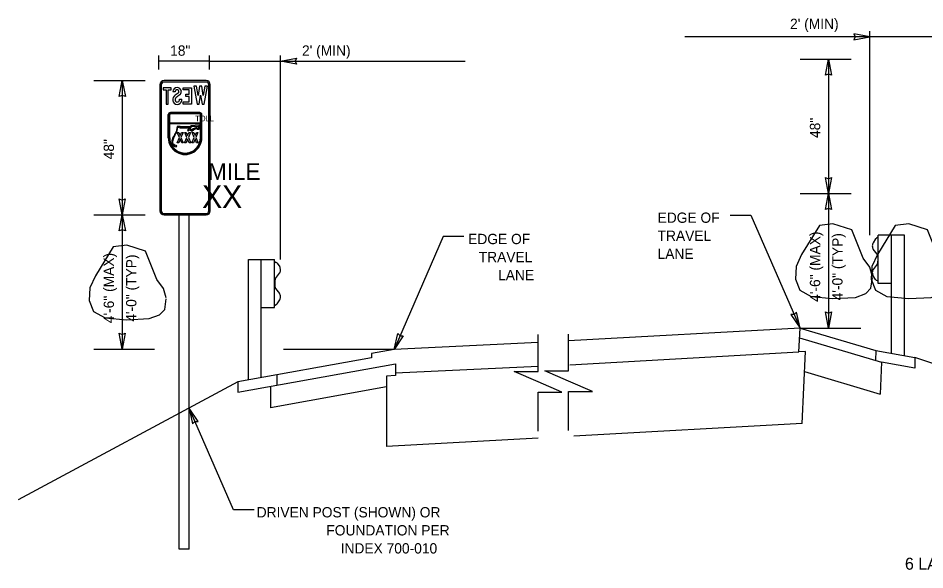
# Model space of a CAD drawing. Extents: x 57428 to 58066, y 11696 to 12105.
# Drawn here: x 57464.3 to 57710.6, y 11954.7 to 12104.5 of the extents above; entities that cross this region are included whole.
import ezdxf

# ---------------------------------------------------------------- set-up
doc = ezdxf.new("R2010")
doc.units = 0
for name, color, linetype in [('52', 7, 'Continuous'), ('62', 7, 'Continuous'), ('Default', 7, 'Continuous'), ('DimLines_dp', 7, 'Continuous'), ('NonPlottingEle_dp', 7, 'Continuous'), ('SignPanel', 7, 'Continuous'), ('TextTables', 7, 'Continuous'), ('XSGrdLine_ex', 7, 'Continuous')]:
    doc.layers.add(name, color=color, linetype=linetype)

msp = doc.modelspace()

# ---------------------------------------------------------------- linework, layer by layer
at = {"layer": '52'}
for p, q in [((57676.68, 12020.37), (57693.18, 12020.37)), ((57484.81, 12014.58), (57501.31, 12014.58)), ((57536.38, 12014.58), (57566.41, 12014.58))]:
    msp.add_line(p, q, dxfattribs=at)
at = {"layer": '62'}
for points in [[(57696.33, 12034.31), (57695.63, 12036.91), (57693.83, 12039.32), (57690.73, 12047.07), (57685.63, 12048.67), (57681.93, 12048.17), (57677.12, 12040.32), (57675.62, 12037.11), (57675.42, 12033.61), (57676.62, 12030.61), (57679.73, 12028.9), (57685.63, 12028.4), (57691.73, 12028.7), (57694.53, 12029.7), (57695.93, 12031.21), (57696.33, 12034.11)], [(57716.92, 12034.31), (57716.22, 12036.91), (57714.42, 12039.32), (57711.32, 12047.07), (57706.22, 12048.67), (57702.51, 12048.17), (57697.71, 12040.32), (57696.21, 12037.11), (57696.01, 12033.61), (57697.21, 12030.61), (57700.31, 12028.9), (57706.22, 12028.4), (57712.32, 12028.7), (57715.12, 12029.7), (57716.52, 12031.21), (57716.92, 12034.11)], [(57504.47, 12028.52), (57503.77, 12031.12), (57501.97, 12033.52), (57498.86, 12041.28), (57493.76, 12042.88), (57490.06, 12042.38), (57485.26, 12034.52), (57483.76, 12031.32), (57483.56, 12027.82), (57484.76, 12024.81), (57487.86, 12023.11), (57493.76, 12022.61), (57499.86, 12022.91), (57502.67, 12023.91), (57504.07, 12025.41), (57504.47, 12028.32)]]:
    msp.add_lwpolyline(points, dxfattribs=at)
at = {"layer": 'Default'}
for points in [[(57605.5, 11992.39), (57605.5, 12002.95), (57611.96, 12002.95), (57605.5, 12005.76), (57599.04, 12008.57), (57605.5, 12008.57), (57605.5, 12018.57)], [(57613.8, 11992.52), (57613.8, 12003.08), (57620.26, 12003.08), (57613.8, 12005.89), (57607.34, 12008.71), (57613.8, 12008.71), (57613.8, 12018.71)]]:
    msp.add_lwpolyline(points, dxfattribs=at)
at = {"layer": 'DimLines_dp'}
for p, q in [((57695.64, 12045.58), (57695.64, 12100.98)), ((57714.97, 12099.43), (57645.43, 12099.43)), ((57695.64, 12099.43), (57691.29, 12100.27)), ((57691.29, 12100.27), (57691.62, 12099.43)), ((57691.62, 12099.43), (57691.29, 12098.62)), ((57691.29, 12098.62), (57695.64, 12099.43)), ((57502.51, 12090.57), (57502.51, 12094.4)), ((57516.2, 12090.57), (57516.2, 12094.4)), ((57535.53, 12039), (57535.53, 12094.4)), ((57535.53, 12092.86), (57539.88, 12093.7)), ((57539.88, 12093.7), (57539.55, 12092.86)), ((57676.68, 12093.37), (57690.6, 12093.37)), ((57683.61, 12089.02), (57684.42, 12093.37)), ((57684.42, 12093.37), (57684.42, 12056.87)), ((57684.42, 12093.37), (57685.26, 12089.02)), ((57516.2, 12092.86), (57502.51, 12092.86)), ((57516.2, 12092.86), (57585.74, 12092.86)), ((57539.88, 12092.05), (57535.53, 12092.86)), ((57539.55, 12092.86), (57539.88, 12092.05)), ((57684.42, 12089.35), (57683.61, 12089.02)), ((57685.26, 12089.02), (57684.42, 12089.35)), ((57484.81, 12087.57), (57498.74, 12087.57)), ((57491.74, 12083.22), (57492.55, 12087.57)), ((57492.55, 12087.57), (57492.55, 12051.07)), ((57492.55, 12087.57), (57493.39, 12083.22)), ((57492.55, 12083.55), (57491.74, 12083.22)), ((57493.39, 12083.22), (57492.55, 12083.55)), ((57684.42, 12056.87), (57683.58, 12061.22)), ((57683.58, 12061.22), (57684.42, 12060.89)), ((57684.42, 12056.87), (57683.58, 12061.22)), ((57683.58, 12061.22), (57684.42, 12060.89)), ((57684.42, 12060.89), (57685.23, 12061.22)), ((57685.23, 12061.22), (57684.42, 12056.87)), ((57684.42, 12060.89), (57685.23, 12061.22)), ((57685.23, 12061.22), (57684.42, 12056.87)), ((57676.68, 12056.87), (57690.6, 12056.87)), ((57683.61, 12052.52), (57684.42, 12056.87)), ((57684.42, 12056.87), (57684.42, 12020.37)), ((57684.42, 12056.87), (57685.26, 12052.52)), ((57492.55, 12051.07), (57491.71, 12055.42)), ((57491.71, 12055.42), (57492.55, 12055.09)), ((57492.55, 12051.07), (57491.71, 12055.42)), ((57491.71, 12055.42), (57492.55, 12055.09)), ((57492.55, 12055.09), (57493.36, 12055.42)), ((57493.36, 12055.42), (57492.55, 12051.07)), ((57492.55, 12055.09), (57493.36, 12055.42)), ((57493.36, 12055.42), (57492.55, 12051.07)), ((57684.42, 12052.85), (57683.61, 12052.52)), ((57685.26, 12052.52), (57684.42, 12052.85)), ((57484.81, 12051.07), (57498.74, 12051.07)), ((57491.74, 12046.72), (57492.55, 12051.07)), ((57492.55, 12051.07), (57492.55, 12014.58)), ((57492.55, 12051.07), (57493.39, 12046.72)), ((57657.71, 12050.98), (57663.36, 12050.98)), ((57663.36, 12050.98), (57676.68, 12020.37)), ((57492.55, 12047.05), (57491.74, 12046.72)), ((57493.39, 12046.72), (57492.55, 12047.05)), ((57579.73, 12045.19), (57566.41, 12014.57)), ((57585.38, 12045.19), (57579.73, 12045.19)), ((57675.71, 12024.69), (57675.08, 12024.05)), ((57676.68, 12020.37), (57675.71, 12024.69)), ((57684.42, 12020.37), (57683.58, 12024.72)), ((57683.58, 12024.72), (57684.42, 12024.39)), ((57684.42, 12024.39), (57685.23, 12024.72)), ((57685.23, 12024.72), (57684.42, 12020.37)), ((57675.08, 12024.05), (57674.2, 12024.03)), ((57674.2, 12024.03), (57676.68, 12020.37)), ((57492.55, 12014.58), (57491.71, 12018.93)), ((57491.71, 12018.93), (57492.55, 12018.6)), ((57492.55, 12018.6), (57493.36, 12018.93)), ((57493.36, 12018.93), (57492.55, 12014.58)), ((57566.41, 12014.57), (57567.37, 12018.9)), ((57568.89, 12018.24), (57566.41, 12014.57)), ((57567.37, 12018.9), (57568.01, 12018.26)), ((57568.01, 12018.26), (57568.89, 12018.24)), ((57522.73, 11970.95), (57510.69, 11998.63)), ((57510.69, 11998.63), (57511.65, 11994.3)), ((57513.17, 11994.96), (57510.69, 11998.63)), ((57511.65, 11994.3), (57512.29, 11994.94)), ((57512.29, 11994.94), (57513.17, 11994.96)), ((57528.38, 11970.95), (57522.73, 11970.95))]:
    msp.add_line(p, q, dxfattribs=at)
at = {"layer": 'NonPlottingEle_dp'}
for p, q in [((57508.03, 11997.2), (57508.03, 12051.07)), ((57510.69, 11998.63), (57510.69, 12051.07)), ((57508.03, 11960.3), (57508.03, 11997.2)), ((57510.69, 11960.3), (57510.69, 11998.63)), ((57510.69, 11960.3), (57508.03, 11960.3))]:
    msp.add_line(p, q, dxfattribs=at)
at = {"layer": 'SignPanel'}
for p, q in [((57506.91, 12084.56), (57506.3, 12084.56)), ((57506.91, 12084.56), (57506.3, 12084.56)), ((57506.91, 12084.56), (57506.3, 12084.56)), ((57508.11, 12082.56), (57508.73, 12082.56)), ((57508.11, 12082.56), (57508.73, 12082.56)), ((57508.11, 12082.56), (57508.73, 12082.56)), ((57513.6, 12078.91), (57505.61, 12078.91)), ((57513.6, 12078.71), (57505.61, 12078.71)), ((57513.6, 12078.52), (57505.61, 12078.52)), ((57505.04, 12072.06), (57505.04, 12078.34)), ((57505.24, 12072.06), (57505.24, 12078.34)), ((57505.43, 12076.05), (57505.43, 12078.34)), ((57513.79, 12076.05), (57505.43, 12076.05)), ((57513.79, 12076.05), (57513.79, 12078.34)), ((57513.98, 12072.06), (57513.98, 12078.34)), ((57514.17, 12072.06), (57514.17, 12078.34)), ((57505.43, 12072.06), (57505.43, 12075.86)), ((57513.79, 12075.86), (57505.43, 12075.86)), ((57507.16, 12073.69), (57506.71, 12072.96)), ((57506.94, 12072.9), (57507.38, 12073.6)), ((57507.49, 12075.12), (57507.16, 12073.69)), ((57507.38, 12073.6), (57507.68, 12074.89)), ((57508.23, 12075.12), (57507.49, 12075.12)), ((57507.68, 12074.89), (57508.11, 12074.89)), ((57508.11, 12074.89), (57508.21, 12074.74)), ((57508.21, 12074.74), (57511.22, 12074.74)), ((57508.33, 12074.97), (57508.23, 12075.12)), ((57511.06, 12074.97), (57508.33, 12074.97)), ((57510.77, 12074.45), (57510.27, 12074.11)), ((57510.27, 12074.11), (57510.4, 12073.92)), ((57510.4, 12073.92), (57510.77, 12074.17)), ((57511.38, 12074.09), (57510.77, 12074.45)), ((57510.77, 12074.17), (57511.41, 12073.8)), ((57511.19, 12075.31), (57511.06, 12074.97)), ((57513.57, 12075.5), (57511.19, 12075.31)), ((57511.22, 12074.74), (57511.36, 12075.09)), ((57511.36, 12075.09), (57513.3, 12075.24)), ((57511.83, 12074.5), (57511.38, 12074.09)), ((57511.41, 12073.8), (57511.95, 12074.3)), ((57512.75, 12074.8), (57511.83, 12074.5)), ((57511.95, 12074.3), (57512.7, 12074.55)), ((57512.32, 12075.16), (57512.32, 12075.16)), ((57512.7, 12074.55), (57512.95, 12074.35)), ((57513.02, 12074.59), (57512.75, 12074.8)), ((57512.95, 12074.35), (57513.41, 12074.41)), ((57513.2, 12074.61), (57513.02, 12074.59)), ((57513.3, 12075.24), (57513.2, 12074.61)), ((57513.41, 12074.41), (57513.57, 12075.5)), ((57513.79, 12072.06), (57513.79, 12075.86)), ((57506.3, 12072.11), (57506.05, 12071.18)), ((57506.05, 12071.18), (57506.05, 12070.32)), ((57506.28, 12071.15), (57506.51, 12072.01)), ((57506.28, 12070.43), (57506.28, 12071.15)), ((57506.71, 12072.78), (57506.3, 12072.11)), ((57506.51, 12072.01), (57506.94, 12072.72)), ((57506.71, 12072.96), (57506.71, 12072.78)), ((57506.94, 12072.72), (57506.94, 12072.9)), ((57506.05, 12070.32), (57506.8, 12069.7)), ((57506.9, 12069.92), (57506.28, 12070.43)), ((57506.8, 12069.7), (57507.16, 12069.62)), ((57507.11, 12069.87), (57506.9, 12069.92)), ((57507.25, 12069.96), (57507.11, 12069.87)), ((57507.16, 12069.62), (57507.38, 12069.78)), ((57507.38, 12069.78), (57507.25, 12069.96))]:
    msp.add_line(p, q, dxfattribs=at)
for points in [[(57502.76, 12086.43), (57502.76, 12052.21)], [(57503.14, 12086.43), (57503.14, 12052.21)], [(57515.31, 12087.57), (57503.9, 12087.57)], [(57515.31, 12087.19), (57503.9, 12087.19)], [(57516.07, 12052.21), (57516.07, 12086.43)], [(57516.45, 12052.21), (57516.45, 12086.43)], [(57503.9, 12051.45), (57515.31, 12051.45)], [(57503.9, 12051.07), (57515.31, 12051.07)]]:
    msp.add_lwpolyline(points, dxfattribs=at)
for points in [[(57514.54, 12083.53), (57514.14, 12086.1), (57513.53, 12086.1), (57513.13, 12083.53), (57512.68, 12086.1), (57511.98, 12086.1), (57512.86, 12081.14), (57513.45, 12081.14), (57513.84, 12083.62), (57514.23, 12081.14), (57514.81, 12081.14), (57515.69, 12086.1), (57515, 12086.1)], [(57514.54, 12083.53), (57514.14, 12086.1), (57513.53, 12086.1), (57513.13, 12083.53), (57512.68, 12086.1), (57511.98, 12086.1), (57512.86, 12081.14), (57513.45, 12081.14), (57513.84, 12083.62), (57514.23, 12081.14), (57514.81, 12081.14), (57515.69, 12086.1), (57515, 12086.1)], [(57514.54, 12083.53), (57514.14, 12086.1), (57513.53, 12086.1), (57513.13, 12083.53), (57512.68, 12086.1), (57511.98, 12086.1), (57512.86, 12081.14), (57513.45, 12081.14), (57513.84, 12083.62), (57514.23, 12081.14), (57514.81, 12081.14), (57515.69, 12086.1), (57515, 12086.1)], [(57505.05, 12085.02), (57505.87, 12085.02), (57505.87, 12085.65), (57503.61, 12085.65), (57503.61, 12085.02), (57504.43, 12085.02), (57504.43, 12081.14), (57505.05, 12081.14)], [(57505.05, 12085.02), (57505.87, 12085.02), (57505.87, 12085.65), (57503.61, 12085.65), (57503.61, 12085.02), (57504.43, 12085.02), (57504.43, 12081.14), (57505.05, 12081.14)], [(57505.05, 12085.02), (57505.87, 12085.02), (57505.87, 12085.65), (57503.61, 12085.65), (57503.61, 12085.02), (57504.43, 12085.02), (57504.43, 12081.14), (57505.05, 12081.14)], [(57510.76, 12081.78), (57510.76, 12083.22), (57509.79, 12083.22), (57509.79, 12083.85), (57510.76, 12083.85), (57510.76, 12085.02), (57509.12, 12085.02), (57509.12, 12085.65), (57511.38, 12085.65), (57511.38, 12081.14), (57509.12, 12081.14), (57509.12, 12081.78)], [(57510.76, 12081.78), (57510.76, 12083.22), (57509.79, 12083.22), (57509.79, 12083.85), (57510.76, 12083.85), (57510.76, 12085.02), (57509.12, 12085.02), (57509.12, 12085.65), (57511.38, 12085.65), (57511.38, 12081.14), (57509.12, 12081.14), (57509.12, 12081.78)], [(57510.76, 12081.78), (57510.76, 12083.22), (57509.79, 12083.22), (57509.79, 12083.85), (57510.76, 12083.85), (57510.76, 12085.02), (57509.12, 12085.02), (57509.12, 12085.65), (57511.38, 12085.65), (57511.38, 12081.14), (57509.12, 12081.14), (57509.12, 12081.78)], [(57508.69, 12070.64), (57508.28, 12071.62), (57507.87, 12070.64), (57507.44, 12070.64), (57508.06, 12072.13), (57507.49, 12073.49), (57507.92, 12073.49), (57508.28, 12072.64), (57508.64, 12073.49), (57509.06, 12073.49), (57508.49, 12072.13), (57509.11, 12070.64)], [(57510.7, 12070.64), (57510.29, 12071.62), (57509.88, 12070.64), (57509.46, 12070.64), (57510.08, 12072.13), (57509.51, 12073.49), (57509.93, 12073.49), (57510.29, 12072.64), (57510.65, 12073.49), (57511.08, 12073.49), (57510.51, 12072.13), (57511.13, 12070.64)], [(57512.72, 12070.64), (57512.31, 12071.62), (57511.9, 12070.64), (57511.47, 12070.64), (57512.1, 12072.13), (57511.52, 12073.49), (57511.95, 12073.49), (57512.31, 12072.64), (57512.67, 12073.49), (57513.09, 12073.49), (57512.52, 12072.13), (57513.14, 12070.64)]]:
    msp.add_lwpolyline(points, close=True, dxfattribs=at)
for centre, radius, start, end in [((57503.9, 12086.43), 1.14, 90, 180), ((57503.9, 12086.43), 0.76, 90, 180), ((57515.31, 12086.43), 1.14, 0, 90), ((57515.31, 12086.43), 0.76, 0, 90), ((57503.9, 12052.21), 1.14, 180, 270), ((57503.9, 12052.21), 0.76, 180, 270), ((57515.31, 12052.21), 1.14, 270, 0), ((57515.31, 12052.21), 0.76, 270, 0)]:
    msp.add_arc(centre, radius, start, end, dxfattribs=at)
for centre, major_axis, ratio, start_param, end_param in [((57507.45, 12084.54), (0, -1.17), 0.981197, 1.634182, 4.688511), ((57507.45, 12084.54), (0, -1.17), 0.981197, 1.634182, 4.688511), ((57507.45, 12084.54), (0, -1.17), 0.981197, 1.634182, 4.688511), ((57509.76, 12080.4), (0, -4.32), 0.981197, 3.642536, 3.961892), ((57509.76, 12080.4), (0, -4.32), 0.981197, 3.642536, 3.961892), ((57509.76, 12080.4), (0, -4.32), 0.981197, 3.642536, 3.961892), ((57507.45, 12084.52), (0, -0.55), 0.981197, 2.28404, 4.637874), ((57507.45, 12084.52), (0, -0.55), 0.981197, 2.28404, 4.637874), ((57507.45, 12084.52), (0, -0.55), 0.981197, 2.28404, 4.637874), ((57510.3, 12079.71), (0, -4.56), 0.981197, 3.63779, 3.909641), ((57510.3, 12079.71), (0, -4.56), 0.981197, 3.63779, 3.909641), ((57510.3, 12079.71), (0, -4.56), 0.981197, 3.63779, 3.909641), ((57507.52, 12084.59), (0, -0.453), 0.981197, 0.484634, 2.267813), ((57507.52, 12084.59), (0, -0.453), 0.981197, 0.484634, 2.267813), ((57507.52, 12084.59), (0, -0.453), 0.981197, 0.484634, 2.267813), ((57507.56, 12084.57), (0, -1.05), 0.981197, 0.629826, 1.606762), ((57507.56, 12084.57), (0, -1.05), 0.981197, 0.629826, 1.606762), ((57507.56, 12084.57), (0, -1.05), 0.981197, 0.629826, 1.606762), ((57507.64, 12082.37), (0, -1.4), 0.981197, 3.939023, 5.163791), ((57507.64, 12082.37), (0, -1.4), 0.981197, 3.939023, 5.163791), ((57507.64, 12082.37), (0, -1.4), 0.981197, 3.939023, 5.163791), ((57507.49, 12082.31), (0, -1.23), 0.981197, 5.173086, 6.638731), ((57507.49, 12082.31), (0, -1.23), 0.981197, 5.173086, 6.638731), ((57507.49, 12082.31), (0, -1.23), 0.981197, 5.173086, 6.638731), ((57507.65, 12082.37), (0, -0.78), 0.981197, 3.79238, 5.170369), ((57507.65, 12082.37), (0, -0.78), 0.981197, 3.79238, 5.170369), ((57507.65, 12082.37), (0, -0.78), 0.981197, 3.79238, 5.170369), ((57507.46, 12082.29), (0, -0.572), 0.981197, 5.194718, 7.162991), ((57507.46, 12082.29), (0, -0.572), 0.981197, 5.194718, 7.162991), ((57507.46, 12082.29), (0, -0.572), 0.981197, 5.194718, 7.162991), ((57507.23, 12082.52), (0, -0.897), 0.981197, 0.859453, 1.616836), ((57507.29, 12082.49), (0, -1.47), 0.981197, 0.439911, 1.615229), ((57507.23, 12082.52), (0, -0.897), 0.981197, 0.859453, 1.616836), ((57507.29, 12082.49), (0, -1.47), 0.981197, 0.439911, 1.615229), ((57507.23, 12082.52), (0, -0.897), 0.981197, 0.859453, 1.616836), ((57507.29, 12082.49), (0, -1.47), 0.981197, 0.439911, 1.615229), ((57505.62, 12078.33), (0, 0.57), 0.9997, 0, 1.570796), ((57505.62, 12078.33), (0, 0.38), 0.9997, 0, 1.570796), ((57505.62, 12078.33), (0, 0.19), 0.9997, 0, 1.570796), ((57513.6, 12078.33), (0, 0.57), 0.9997, 4.712389, 6.283185), ((57513.6, 12078.33), (0, 0.38), 0.9997, 4.712389, 6.283185), ((57513.6, 12078.33), (0, 0.19), 0.9997, 4.712389, 6.283185), ((57509.61, 12072.06), (0, 4.56), 0.9997, 1.570796, 4.712389), ((57509.61, 12072.06), (0, 4.37), 0.9997, 1.570796, 4.712389), ((57509.61, 12072.06), (0, 4.18), 0.9997, 1.570796, 4.712389)]:
    msp.add_ellipse(centre, major_axis=major_axis, ratio=ratio, start_param=start_param, end_param=end_param, dxfattribs=at)
at = {"layer": 'XSGrdLine_ex'}
for p, q in [((57697.23, 12044.57), (57696.53, 12043.53)), ((57697.92, 12045.01), (57697.45, 12044.78)), ((57705.04, 12045.58), (57697.93, 12045.58)), ((57697.93, 12032.49), (57697.93, 12045.58)), ((57701.54, 12013.47), (57701.54, 12045.58)), ((57705.04, 12012.84), (57705.04, 12045.58)), ((57697.63, 12040.42), (57696.56, 12041.82)), ((57697.86, 12039.6), (57697.86, 12038.5)), ((57526.81, 12006.27), (57526.81, 12039)), ((57526.81, 12039), (57533.91, 12039)), ((57530.3, 12006.9), (57530.3, 12039)), ((57533.91, 12025.91), (57533.91, 12039)), ((57533.92, 12038.43), (57534.39, 12038.2)), ((57534.62, 12037.99), (57535.31, 12036.95)), ((57697.63, 12037.7), (57696.56, 12036.29)), ((57534.21, 12033.84), (57535.28, 12035.24)), ((57697.23, 12033.54), (57696.53, 12034.57)), ((57533.99, 12033.02), (57533.99, 12031.92)), ((57697.92, 12033.1), (57697.45, 12033.31)), ((57701.54, 12032.49), (57697.93, 12032.49)), ((57534.21, 12031.12), (57535.28, 12029.71)), ((57533.92, 12026.52), (57534.39, 12026.73)), ((57534.62, 12026.96), (57535.31, 12027.99)), ((57530.3, 12025.91), (57533.91, 12025.91)), ((57676.68, 12020.37), (57613.8, 12016.89)), ((57676.39, 12013.86), (57676.68, 12020.37)), ((57676.68, 12020.37), (57697.32, 12014.23)), ((57676.56, 12017.7), (57698.85, 12011.07)), ((57566.41, 12014.57), (57560.25, 12013.46)), ((57560.25, 12012.29), (57523.97, 12005.76)), ((57560.25, 12013.46), (57560.25, 12012.29)), ((57614.16, 12010.41), (57676.39, 12013.86)), ((57678.14, 12013.95), (57676.39, 12013.86)), ((57677.27, 11994.41), (57678.14, 12013.95)), ((57697.32, 12014.23), (57697.2, 12011.56)), ((57697.32, 12014.23), (57707.87, 12012.33)), ((57751.86, 11997.83), (57707.87, 12012.33)), ((57707.87, 12012.33), (57707.87, 12009.5)), ((57523.97, 12002.92), (57566.82, 12010.63)), ((57566.82, 12010.63), (57566.82, 12007.48)), ((57698.85, 12011.07), (57698.47, 12002.43)), ((57707.87, 12009.5), (57698.85, 12011.12)), ((57534.53, 12007.66), (57534.53, 12004.82)), ((57566.82, 12007.48), (57564.35, 12007.33)), ((57564.35, 12007.33), (57564.35, 11988.15)), ((57677.9, 12008.55), (57698.47, 12002.43)), ((57523.97, 12005.76), (57464.25, 11973.7)), ((57523.97, 12005.76), (57523.97, 12002.92)), ((57532.83, 12004.51), (57532.83, 11998.7)), ((57564.35, 12004.37), (57532.83, 11998.7)), ((57677.27, 11994.41), (57615.23, 11990.97)), ((57605.5, 11990.43), (57564.35, 11988.15))]:
    msp.add_line(p, q, dxfattribs=at)
for points in [[(57605.5, 12016.43), (57566.41, 12014.57)], [(57605.5, 12009.93), (57566.82, 12008.09)]]:
    msp.add_lwpolyline(points, dxfattribs=at)
for centre, major_axis, start_param, end_param in [((57697.61, 12043.53), (0, 1.28), 0.24129, 0.636649), ((57696.84, 12042.69), (0, -1.05), 3.777871, 5.70598), ((57697.37, 12039.59), (0, 0.976), 4.723749, 5.70602), ((57534.24, 12036.95), (0, 1.28), 5.646537, 6.041895), ((57535, 12036.11), (0, -1.05), 0.577206, 2.505315), ((57697.37, 12038.51), (0, 0.976), 3.718758, 4.701029), ((57696.84, 12035.41), (0, 1.05), 0.577206, 2.505315), ((57534.48, 12033.01), (0, -0.976), 3.718758, 4.701029), ((57534.48, 12031.93), (0, -0.976), 4.723749, 5.70602), ((57697.61, 12034.56), (0, -1.28), 5.646537, 6.041895), ((57535, 12028.83), (0, 1.05), 3.777871, 5.70598), ((57534.24, 12027.99), (0, -1.28), 0.24129, 0.636649)]:
    msp.add_ellipse(centre, major_axis=major_axis, ratio=0.5, start_param=start_param, end_param=end_param, dxfattribs=at)

# ---------------------------------------------------------------- texts
at = {"layer": 'DimLines_dp'}
for s, p in [("2' (MIN)", (57673.97, 12101.59)), ('18"', (57505.55, 12094.33)), ("2' (MIN)", (57541.38, 12094.33)), ('EDGE OF ', (57637.98, 12048.94)), ('TRAVEL ', (57637.98, 12044.04)), ('EDGE OF ', (57586.52, 12043.15)), ('LANE', (57637.98, 12039.14)), ('TRAVEL ', (57589.39, 12038.25)), ('LANE', (57594.65, 12033.35)), ('DRIVEN POST (SHOWN) OR', (57529.06, 11968.92)), ('FOUNDATION PER', (57547.99, 11964.02)), ('INDEX 700-010', (57551.88, 11959.12))]:
    msp.add_text(s, height=2.8, dxfattribs=at).set_placement(p)
for s, p in [('48"', (57682.16, 12071.98)), ('48"', (57490.29, 12066.18)), ('4\'-6" (MAX)', (57682.16, 12027.47)), ('4\'-0" (TYP)', (57688.24, 12027.87)), ('4\'-6" (MAX)', (57490.29, 12021.67)), ('4\'-0" (TYP)', (57496.38, 12022.07))]:
    msp.add_text(s, height=2.8, rotation=90, dxfattribs=at).set_placement(p)
at = {"layer": 'SignPanel'}
for s, height, p in [('TOLL', 1.519, (57512.36, 12076.53)), ('MILE', 4.562, (57515.86, 12060.57)), ('XX', 6.083, (57514.25, 12053.01))]:
    msp.add_text(s, height=height, dxfattribs=at).set_placement(p)
at = {"layer": 'TextTables'}
msp.add_text("6 LANES OR MORE - MEDIANS 40' OR LESS", height=3.2524, dxfattribs=at).set_placement((57705.19, 11954.72))

doc.saveas('drawing.dxf')
